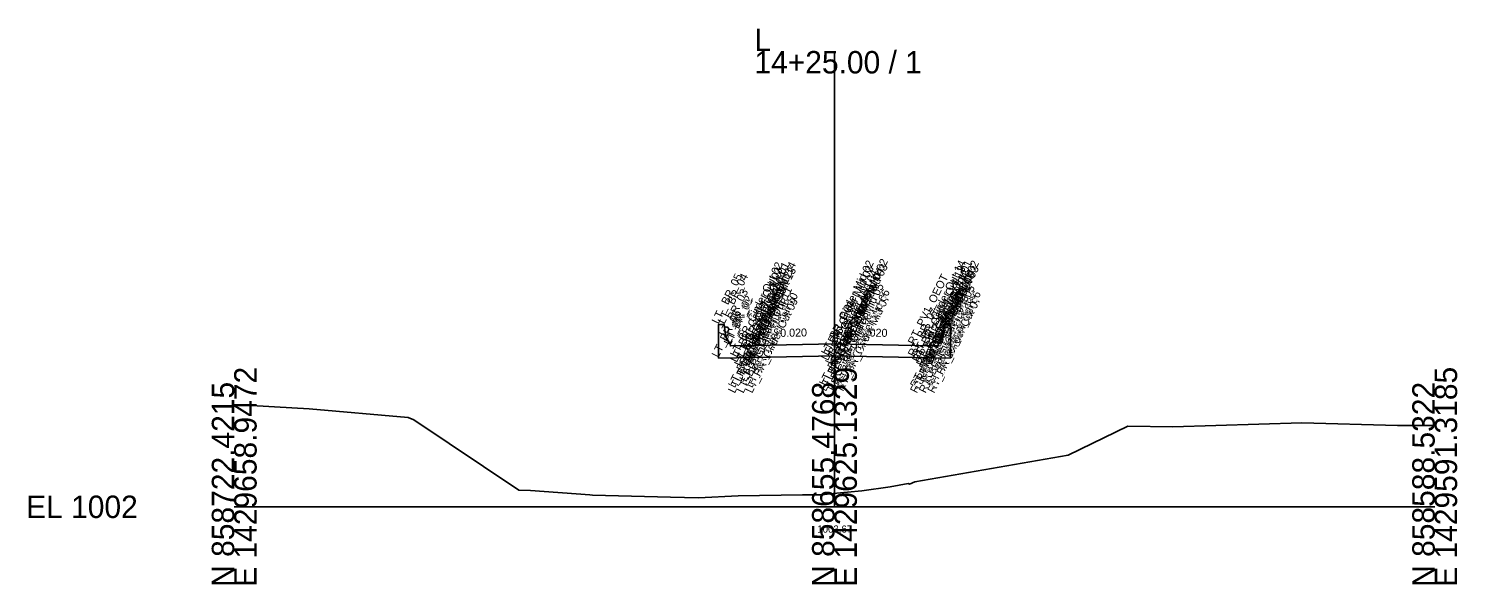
# Model space of a CAD drawing. Extents: x -26 to 153, y -10 to 13058.
# Drawn here: x -25.7 to 152.8, y 5490.3 to 5559.7 of the extents above; entities that cross this region are included whole.
import ezdxf

# ---------------------------------------------------------------- set-up
doc = ezdxf.new("R2010")
doc.units = 0
for name, color, linetype in [('Default', 7, 'Continuous'), ('Exist Cross Section Cell', 7, 'Continuous'), ('Exist XS Center Line Elevation Label', 7, 'Continuous'), ('Exist XS Ground Line', 7, 'Continuous'), ('Prop CMT Concrete Structures', 7, 'Continuous'), ('Prop XS Dump Level', 7, 'Continuous'), ('Prop XS SE Text', 7, 'Continuous')]:
    doc.layers.add(name, color=color, linetype=linetype)

msp = doc.modelspace()

# ---------------------------------------------------------------- linework, layer by layer
at = {"layer": 'Exist Cross Section Cell'}
for p, q in [((75, 5500), (75, 5556.93)), ((0, 5500), (75, 5500)), ((75, 5500), (150, 5500))]:
    msp.add_line(p, q, dxfattribs=at)
at = {"layer": 'Exist XS Ground Line'}
msp.add_lwpolyline([(0, 5512.79), (9.35, 5512.25), (21.72, 5511.16), (22.46, 5510.85), (35.55, 5502.07), (37.01, 5502.03), (44.44, 5501.49), (44.78, 5501.47), (54.52, 5501.19), (58.03, 5501.14), (62.99, 5501.38), (71.01, 5501.48), (73.39, 5501.51), (74.84, 5501.66), (78.42, 5502.01), (81.97, 5502.51), (84.22, 5502.92), (84.36, 5502.82), (85.04, 5503.11), (104.21, 5506.46), (111.64, 5510.06), (117.26, 5509.98), (133.39, 5510.5), (145.37, 5510.16), (149.53, 5510.15), (150, 5510.14)], dxfattribs=at)
at = {"layer": 'Prop CMT Concrete Structures'}
for points in [[(75, 5520.35), (65, 5520.15), (62, 5520.09), (61.99, 5520.34), (61.41, 5521.17), (61.24, 5522.76), (60.5, 5522.76), (60.5, 5518.56)], [(75, 5520.35), (85, 5520.15), (88, 5520.09), (88.01, 5520.34), (88.59, 5521.17), (88.76, 5522.76), (89.5, 5522.76), (89.5, 5518.56)], [(75, 5518.85), (75, 5520.35)], [(75, 5518.85), (75, 5520.35)], [(60.5, 5518.56), (65, 5518.65), (75, 5518.85)], [(89.5, 5518.56), (85, 5518.65), (75, 5518.85)]]:
    msp.add_lwpolyline(points, dxfattribs=at)

# ---------------------------------------------------------------- texts
at = {"layer": 'Default'}
msp.add_text('-', height=0.0001, dxfattribs=at).set_placement((0, 5500))
at = {"layer": 'Exist Cross Section Cell'}
for s, p in [('L', (65, 5556.93)), ('14+25.00 / 1', (65, 5554.13)), ('EL 1002', (-26, 5498.6))]:
    msp.add_text(s, height=2.8, dxfattribs=at).set_placement(p)
for s, p in [('E 1429658.9472', (2.8, 5490)), ('E 1429625.1329', (77.8, 5490)), ('E 1429591.3185', (152.8, 5490)), ('N 858722.4215', (0, 5490)), ('N 858655.4768', (75, 5490)), ('N 858588.5322', (150, 5490))]:
    msp.add_text(s, height=2.8, rotation=90, dxfattribs=at).set_placement(p)
at = {"layer": 'Exist XS Center Line Elevation Label'}
msp.add_text('1003.67', height=0.9, dxfattribs=at).set_placement((72.86, 5496.77))
msp.add_text('1003.67', height=0.9, dxfattribs=at).set_placement((72.86, 5496.77))
msp.add_text('1003.67', height=0.9, dxfattribs=at).set_placement((72.86, 5496.77))
at = {"layer": 'Prop XS Dump Level'}
for s, p in [('RT_BR_Girder Mid 02', (75.83, 5518.83)), ('LT_ BR_05', (60.5, 5522.76)), ('LT_BR_Girder Out 02', (62.79, 5518.61)), ('LT_BR_Girder Out 03', (62.79, 5517.96)), ('LT_BR_Girder Out 04', (63.29, 5517.46)), ('LT_BR_Girder Out 01', (63.62, 5518.62)), ('LT_BR_Girder Out 12', (63.96, 5517.46)), ('LT_BR_Girder Out 14', (64.46, 5518.64)), ('LT_BR_Girder Out 13', (64.46, 5517.96)), ('LT_BR_Girder Mid 02', (74.17, 5518.83)), ('LT_BR_Girder Mid 03', (74.17, 5518.18)), ('LT_BR_Girder Mid 04', (74.67, 5517.68)), ('RT_BR_Girder Mid 04', (75.33, 5517.68)), ('RT_BR_Girder Mid 03', (75.83, 5518.18)), ('RT_BR_Girder Out 14', (85.54, 5518.64)), ('RT_BR_Girder Out 13', (85.54, 5517.96)), ('RT_BR_Girder Out 12', (86.04, 5517.46)), ('RT_BR_Girder Out 01', (86.38, 5518.62)), ('RT_BR_Girder Out 04', (86.71, 5517.46)), ('RT_BR_Girder Out 02', (87.21, 5518.61)), ('RT_BR_Girder Out 03', (87.21, 5517.96)), ('RT_ BR_04', (88.76, 5522.76)), ('RT_ BR_05', (89.5, 5522.76)), ('LT_ BR_04', (61.24, 5522.76)), ('LT_BR_Girder Out 05', (63.29, 5515.54)), ('LT_BR_Girder Out 11', (63.96, 5515.54)), ('LT_PV1_OEOT', (65, 5520.15)), ('LT_BR_Girder Mid 05', (74.67, 5515.77)), ('RT_BR_Girder Mid 05', (75.33, 5515.77)), ('RT_PV1_OEOT', (85, 5520.15)), ('RT_BR_Girder Out 11', (86.04, 5515.54)), ('RT_BR_Girder Out 05', (86.71, 5515.54)), ('RT_BR_03', (88.59, 5521.17)), ('LT_BR_03', (61.41, 5521.17)), ('LT_BR_02', (61.99, 5520.34)), ('LT_BR_01', (62, 5520.09)), ('LT_BR_Girder Out 06', (62.54, 5514.79)), ('LT_BR_Girder Out 07', (62.54, 5514.12)), ('LT_BR_Girder Out 08', (63.62, 5514.12)), ('LT_BR_Girder Out 10', (64.71, 5514.79)), ('LT_BR_Girder Out 09', (64.71, 5514.12)), ('LT_BR_Girder Mid 06', (73.92, 5515.02)), ('LT_BR_Girder Mid 07', (73.92, 5514.35)), ('PV1_PGL', (75, 5520.35)), ('RT_BR_Girder Mid 06', (76.08, 5515.02)), ('RT_BR_Girder Mid 07', (76.08, 5514.35)), ('RT_BR_Girder Out 10', (85.29, 5514.79)), ('RT_BR_Girder Out 09', (85.29, 5514.12)), ('RT_BR_Girder Out 08', (86.38, 5514.12)), ('RT_BR_Girder Out 06', (87.46, 5514.79)), ('RT_BR_Girder Out 07', (87.46, 5514.12)), ('RT_BR_01', (88, 5520.09)), ('RT_BR_02', (88.01, 5520.34)), ('LT_BR_06', (60.5, 5518.56)), ('LT_BR_07', (65, 5518.65)), ('BR_Girder Mid 08', (75, 5514.35)), ('RT_BR_07', (85, 5518.65)), ('RT_BR_06', (89.5, 5518.56)), ('BR_PGL', (75, 5518.85))]:
    msp.add_text(s, height=1, rotation=63.5833, dxfattribs=at).set_placement(p)
at = {"layer": 'Prop XS SE Text'}
for rotation, p in [(1.1458, (68.23, 5521.22)), (358.8542, (78.27, 5521.29))]:
    msp.add_text('0.020', height=1, rotation=rotation, dxfattribs=at).set_placement(p)

doc.saveas('drawing.dxf')
